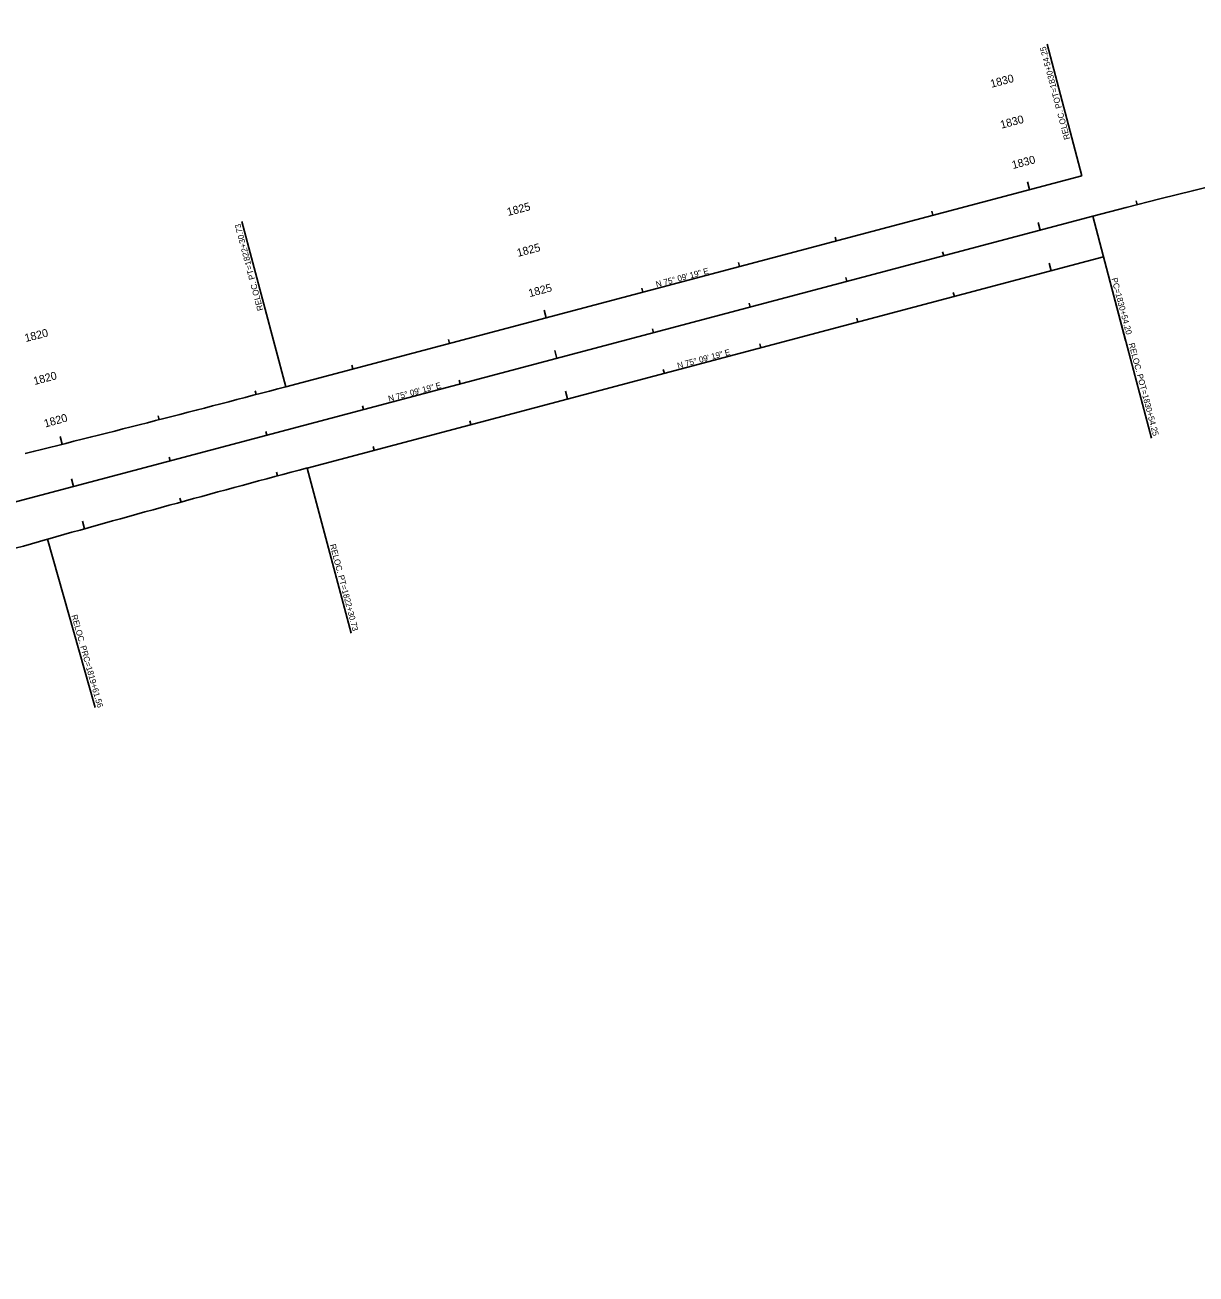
# Model space of a CAD drawing. Extents: x 2106154 to 2121963, y 864504 to 868517.
# Drawn here: x 2113010 to 2114181, y 867153 to 868401 of the extents above; entities that cross this region are included whole.
import ezdxf

# ---------------------------------------------------------------- set-up
doc = ezdxf.new("R2010")
doc.units = 0
for name, color, linetype in [('RD_HC_Cl', 7, 'Continuous'), ('RD_HC_CL_Rel', 7, 'Continuous'), ('RD_HC_Data', 7, 'Continuous'), ('RD_HC_Data_Rel', 7, 'Continuous'), ('RD_HC_Data_Tic', 7, 'Continuous'), ('RD_HC_Data_Tic_Rel', 7, 'Continuous'), ('RD_HC_TX_Rel_Sta50', 7, 'Continuous'), ('RD_HC_TX_Sta50', 7, 'Continuous')]:
    doc.layers.add(name, color=color, linetype=linetype)

msp = doc.modelspace()

# ---------------------------------------------------------------- linework, layer by layer
at = {"layer": 'RD_HC_Cl'}
msp.add_line((2110088.7, 867152.7), (2114077.7, 868210), dxfattribs=at)
msp.add_arc((2115545.6, 862671.7), 5729.6, 82.67967, 104.84478, dxfattribs=at)
at = {"layer": 'RD_HC_CL_Rel'}
for p, q in [((2113270.9, 868039.6), (2114066.9, 868250.6)), ((2113292.4, 867958.4), (2114088.5, 868169.4))]:
    msp.add_line(p, q, dxfattribs=at)
for centre, start, end in [((2109146.1, 883602.3), 283.88688, 284.84478), ((2117417.3, 852395.8), 104.84478, 105.80269), ((2108648.4, 883378.8), 284.84478, 285.80269)]:
    msp.add_arc(centre, 16100, start, end, dxfattribs=at)
at = {"layer": 'RD_HC_Data'}
msp.add_line((2114077.7, 868210), (2114110.6, 868085.9), dxfattribs=at)
at = {"layer": 'RD_HC_Data_Rel'}
for p, q in [((2114066.9, 868250.6), (2114032.1, 868382)), ((2113270.9, 868039.6), (2113227.1, 868204.8)), ((2114088.5, 868169.4), (2114136.5, 867988.1)), ((2113292.4, 867958.4), (2113336.2, 867793.2)), ((2113032.8, 867887.3), (2113080.5, 867719))]:
    msp.add_line(p, q, dxfattribs=at)
at = {"layer": 'RD_HC_Data_Tic'}
for p, q in [((2114122, 868221.6), (2114121, 868225.4)), ((2114025.3, 868196.1), (2114023.3, 868203.9)), ((2113928.7, 868170.5), (2113927.6, 868174.4)), ((2113832, 868144.9), (2113831, 868148.7)), ((2113735.3, 868119.3), (2113734.3, 868123.1)), ((2113638.7, 868093.6), (2113637.6, 868097.5)), ((2113542, 868068), (2113540, 868075.8)), ((2113445.3, 868042.4), (2113444.3, 868046.3)), ((2113348.7, 868016.8), (2113347.7, 868020.6)), ((2113252, 867991.2), (2113251, 867995)), ((2113155.4, 867965.5), (2113154.3, 867969.4)), ((2113058.7, 867939.9), (2113056.6, 867947.7))]:
    msp.add_line(p, q, dxfattribs=at)
at = {"layer": 'RD_HC_Data_Tic_Rel'}
for p, q in [((2114014.5, 868236.7), (2114012.5, 868244.4)), ((2113917.8, 868211.1), (2113916.8, 868215)), ((2113821.2, 868185.5), (2113820.2, 868189.3)), ((2113724.5, 868159.8), (2113723.5, 868163.7)), ((2114036, 868155.5), (2114034, 868163.2)), ((2113627.9, 868134.2), (2113626.8, 868138.1)), ((2113939.4, 868129.9), (2113938.3, 868133.8)), ((2113531.2, 868108.6), (2113529.1, 868116.3)), ((2113842.7, 868104.3), (2113841.7, 868108.1)), ((2113434.5, 868083), (2113433.5, 868086.9)), ((2113746, 868078.6), (2113745, 868082.5)), ((2113337.9, 868057.4), (2113336.8, 868061.2)), ((2113649.4, 868053), (2113648.3, 868056.9)), ((2113241.2, 868031.8), (2113240.2, 868035.6)), ((2113552.7, 868027.4), (2113550.7, 868035.1)), ((2113144.4, 868006.6), (2113143.4, 868010.5)), ((2113456, 868001.8), (2113455, 868005.7)), ((2113047.5, 867982.1), (2113045.5, 867989.9)), ((2113359.4, 867976.2), (2113358.4, 867980)), ((2113262.7, 867950.5), (2113261.7, 867954.4)), ((2113166.2, 867924.4), (2113165.1, 867928.3)), ((2113069.8, 867897.7), (2113067.7, 867905.4))]:
    msp.add_line(p, q, dxfattribs=at)

# ---------------------------------------------------------------- texts
at = {"layer": 'RD_HC_Data'}
for s, rotation, p in [('PC=1830+54.20', 284.8448, (2114096.3, 868147.7)), ('N 75%%d 09\' 19" E', 14.8448, (2113374.2, 868024.6))]:
    msp.add_text(s, height=6, rotation=rotation, dxfattribs=at).set_placement(p)
at = {"layer": 'RD_HC_Data_Rel'}
for s, rotation, p in [('RELOC. POT=1830+54.25', 104.8448, (2114055.1, 868287.5)), ('RELOC. PT=1822+30.73', 104.8448, (2113248.5, 868116.4)), ('N 75%%d 09\' 19" E', 14.8448, (2113641.7, 868138.9)), ('N 75%%d 09\' 19" E', 14.8448, (2113663.2, 868057.7)), ('RELOC. POT=1830+54.25', 284.8448, (2114113.5, 868082.6)), ('RELOC. PT=1822+30.73', 284.8448, (2113314.9, 867881.6)), ('RELOC. PRC=1819+61.56', 285.8027, (2113056.5, 867810.9))]:
    msp.add_text(s, height=6, rotation=rotation, dxfattribs=at).set_placement(p)
at = {"layer": 'RD_HC_TX_Rel_Sta50'}
for s, rotation, p in [('1830', 14.8448, (2113976.5, 868338.4)), ('1830', 14.8448, (2113998, 868257.2)), ('1825', 14.8448, (2113493.2, 868210.3)), ('1825', 14.8448, (2113514.7, 868129.1)), ('1820', 14.0237, (2113010.9, 868084.3)), ('1820', 15.6659, (2113030.4, 867998.8))]:
    msp.add_text(s, height=8, rotation=rotation, dxfattribs=at).set_placement(p)
at = {"layer": 'RD_HC_TX_Sta50'}
for s, p in [('1830', (2113986.4, 868297.5)), ('1825', (2113503.1, 868169.4)), ('1820', (2113019.7, 868041.3))]:
    msp.add_text(s, height=8, rotation=14.8448, dxfattribs=at).set_placement(p)

doc.saveas('drawing.dxf')
